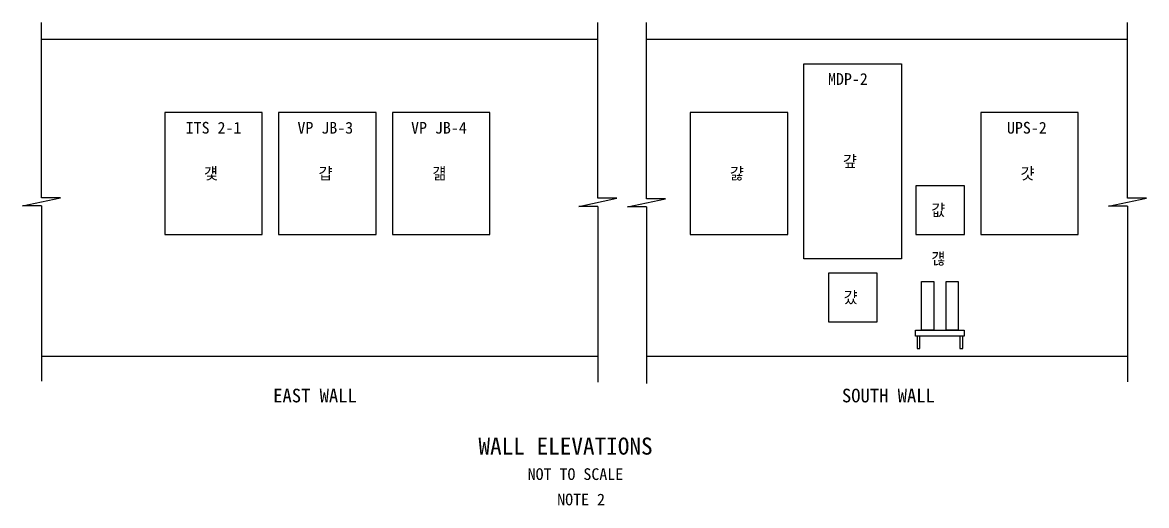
# Model space of a CAD drawing. Extents: x -0.4 to 22.7, y -3.1 to 6.8.
import ezdxf

# ---------------------------------------------------------------- set-up
doc = ezdxf.new("R2010")
doc.units = 0
for name, color, linetype in [('HS_Dimensions and Text', 7, 'Continuous'), ('HS_Electrical_Devices', 7, 'Continuous'), ('HS_Electrical_Enclosure', 7, 'Continuous'), ('HS_Miscellaneous', 7, 'Continuous'), ('Sheets_General Details - Total Sheet Number Text', 7, 'Continuous')]:
    doc.layers.add(name, color=color, linetype=linetype)

msp = doc.modelspace()

# ---------------------------------------------------------------- linework, layer by layer
at = {"layer": 'HS_Dimensions and Text'}
for p, q in [((0, 3.251), (0, 6.847)), ((11.41, 3.241), (11.41, 6.847)), ((12.41, 3.229), (12.41, 6.847)), ((22.273, 3.247), (22.273, 6.847)), ((-0.388, 3.085), (0.388, 3.251)), ((0.388, 3.251), (0, 3.251)), ((11.021, 3.074), (11.798, 3.241)), ((11.798, 3.241), (11.41, 3.241)), ((12.021, 3.063), (12.798, 3.229)), ((12.798, 3.229), (12.41, 3.229)), ((21.885, 3.08), (22.661, 3.247)), ((22.661, 3.247), (22.273, 3.247)), ((0, 3.085), (-0.388, 3.085)), ((0, 3.085), (0, -0.511)), ((11.41, 3.074), (11.021, 3.074)), ((11.41, 3.074), (11.41, -0.533)), ((12.41, 3.063), (12.021, 3.063)), ((12.41, 3.063), (12.41, -0.555)), ((22.273, 3.08), (21.885, 3.08)), ((22.273, 3.08), (22.273, -0.52))]:
    msp.add_line(p, q, dxfattribs=at)
at = {"layer": 'HS_Electrical_Devices'}
for points in [[(17.929, 2.5), (18.929, 2.5), (18.929, 3.5), (17.929, 3.5)], [(16.137, 0.709), (17.137, 0.709), (17.137, 1.709), (16.137, 1.709)], [(18.3, 0.537), (18.05, 0.537), (18.05, 1.537), (18.3, 1.537)], [(18.8, 0.537), (18.55, 0.537), (18.55, 1.537), (18.8, 1.537)], [(17.925, 0.537), (18.925, 0.537), (18.925, 0.412), (17.925, 0.412)], [(18.015, 0.412), (17.955, 0.412), (17.955, 0.162), (18.015, 0.162)], [(18.895, 0.412), (18.835, 0.412), (18.835, 0.162), (18.895, 0.162)]]:
    msp.add_lwpolyline(points, close=True, dxfattribs=at)
at = {"layer": 'HS_Electrical_Enclosure'}
for points in [[(15.637, 6), (17.637, 6), (17.637, 2), (15.637, 2)], [(2.53, 2.5), (4.53, 2.5), (4.53, 5), (2.53, 5)], [(4.864, 2.5), (6.864, 2.5), (6.864, 5), (4.864, 5)], [(7.197, 2.5), (9.197, 2.5), (9.197, 5), (7.197, 5)], [(13.304, 2.5), (15.304, 2.5), (15.304, 5), (13.304, 5)], [(19.262, 2.5), (21.262, 2.5), (21.262, 5), (19.262, 5)]]:
    msp.add_lwpolyline(points, close=True, dxfattribs=at)
at = {"layer": 'HS_Miscellaneous'}
for p, q in [((11.41, 6.5), (0, 6.5)), ((22.273, 6.5), (12.41, 6.5)), ((11.41, 0), (0, 0)), ((22.273, 0), (12.41, 0))]:
    msp.add_line(p, q, dxfattribs=at)

# ---------------------------------------------------------------- texts
at = {"layer": 'Sheets_General Details - Total Sheet Number Text'}
for s, height, p in [('MDP-2', 0.24, (16.13, 5.568)), ('ITS 2-1', 0.24, (2.958, 4.568)), ('VP JB-3', 0.24, (5.25, 4.568)), ('VP JB-4', 0.24, (7.58, 4.568)), ('UPS-2', 0.24, (19.799, 4.568)), ('걒', 0.24, (16.436, 3.88)), ('걫', 0.24, (3.332, 3.63)), ('걉', 0.24, (5.681, 3.63)), ('걞', 0.24, (8.017, 3.63)), ('걇', 0.24, (14.119, 3.63)), ('걋', 0.24, (20.078, 3.63)), ('걊', 0.24, (18.248, 2.88)), ('걚', 0.24, (18.249, 1.884)), ('걌', 0.24, (16.451, 1.089)), ('EAST WALL', 0.28, (4.753, -0.944)), ('SOUTH WALL', 0.28, (16.416, -0.944)), ('WALL ELEVATIONS', 0.35, (8.962, -2.016)), ('NOT TO SCALE ', 0.24, (9.971, -2.536)), ('NOTE 2', 0.24, (10.577, -3.056))]:
    msp.add_text(s, height=height, dxfattribs=at).set_placement(p)

doc.saveas('drawing.dxf')
